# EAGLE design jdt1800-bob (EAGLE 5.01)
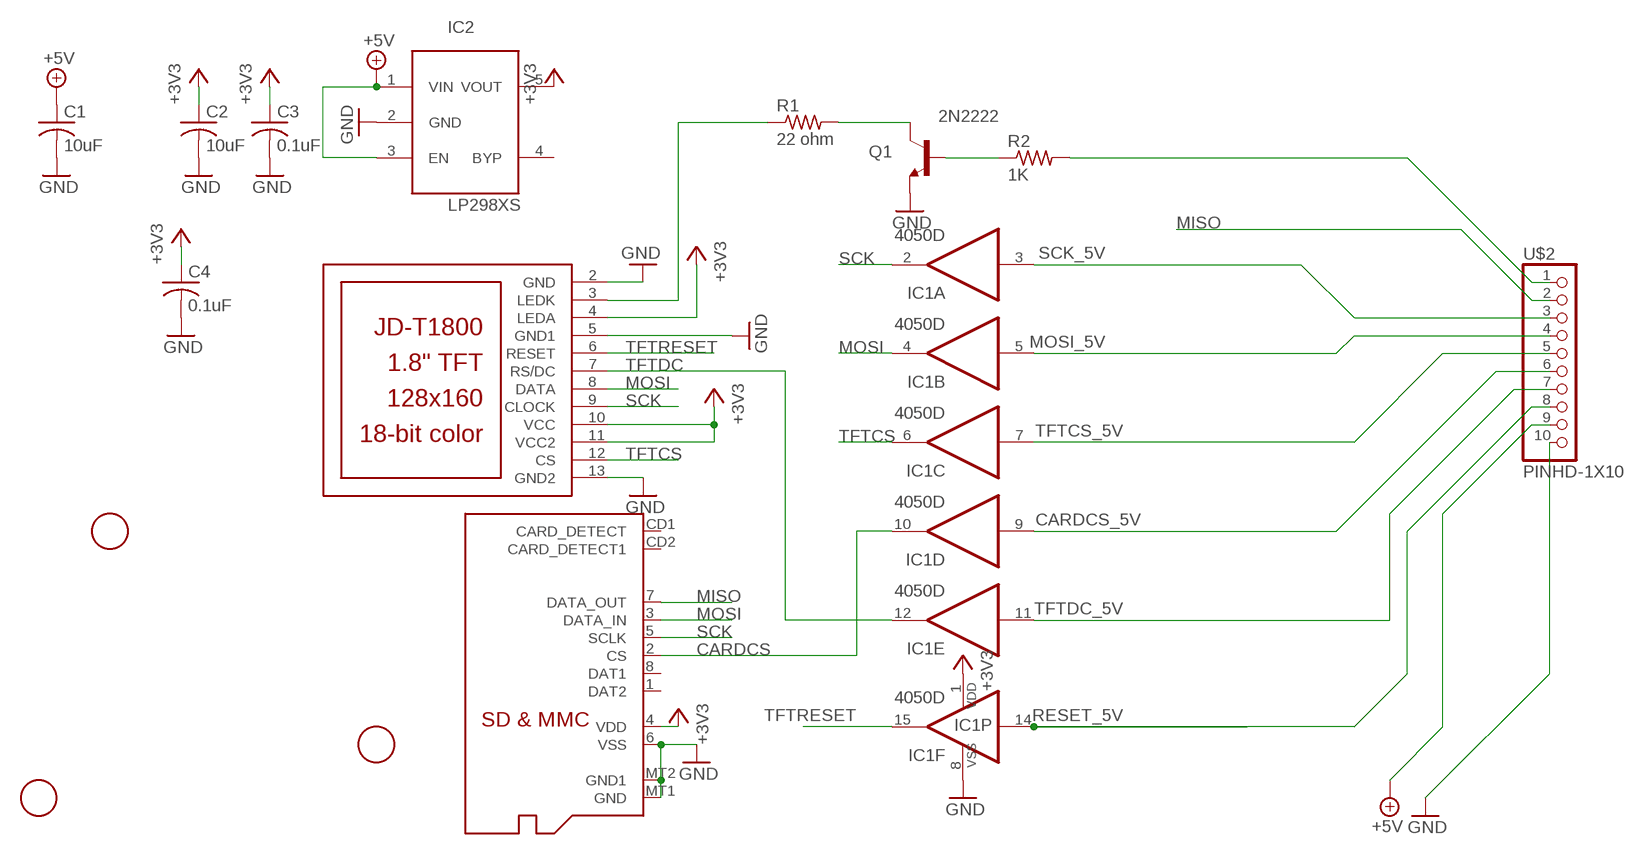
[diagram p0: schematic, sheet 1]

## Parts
C1  10uF  C-USC0805K  [C0805K]
C2  10uF  C-USC0805K  [C0805K]
C3  0.1uF  C-USC0805K  [C0805K]
C4  0.1uF  C-USC0805K  [C0805K]
IC1  4050D  [SO16]
IC2  LP298XS  [SOT23-5L]
Q1  2N2222  MMBT2222ALT1-NPN-SOT23-BEC  [SOT23-BEC]
Q2  MICROSD  [MICROSD]
R1  22 ohm  R-US_R0805  [R0805]
R2  1K  R-US_R0805  [R0805]
U$1  JD-T1800  [JD-T1800]
U$2  PINHD-1X10  [1X10-BIG]
U$3  FIDUCIAL  [FIDUCIAL_1MM]
U$4  FIDUCIAL  [FIDUCIAL_1MM]
U$5  FIDUCIAL  [FIDUCIAL_1MM]

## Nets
+3V3 [power]: C2.1 C3.1 C4.1 IC1.1(P:VDD) IC2.5(VOUT) Q2.4(VDD) U$1.4(LEDA) U$1.10(VCC) U$1.11(VCC2)
+5V [power]: C1.1 IC2.1(VIN) IC2.3(EN) U$2.9
CARDCS: IC1.10(D:O) Q2.2(CS)
CARDCS_5V: IC1.9(D:I) U$2.6
GND: C1.2 C2.2 C3.2 C4.2 IC1.8(P:VSS) IC2.2(GND) Q1.E Q2.6(VSS) Q2.MT1(GND) Q2.MT2(GND1) U$1.2(GND) U$1.5(GND1) U$1.13(GND2) U$2.10
MISO: Q2.7(DATA_OUT) U$2.2
MOSI: IC1.4(B:O) Q2.3(DATA_IN) U$1.8(DATA)
MOSI_5V: IC1.5(B:I) U$2.4
N$1: Q1.B R2.1
N$4: R1.1 U$1.3(LEDK)
N$5: Q1.C R1.2
N$6: R2.2 U$2.1
RESET_5V: IC1.14(F:I) U$2.8
SCK: IC1.2(A:O) Q2.5(SCLK) U$1.9(CLOCK)
SCK_5V: IC1.3(A:I) U$2.3
TFTCS: IC1.6(C:O) U$1.12(CS)
TFTCS_5V: IC1.7(C:I) U$2.5
TFTDC: IC1.12(E:O) U$1.7(RS/DC)
TFTDC_5V: IC1.11(E:I) U$2.7
TFTRESET: IC1.15(F:O) U$1.6(RESET)
Unconnected: IC2.4(BYP) Q2.1(DAT2) Q2.8(DAT1) Q2.CD1(CARD_DETECT) Q2.CD2(CARD_DETECT1)

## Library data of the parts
C1-C4 = rcl:C-US: CAPACITOR, American symbol
IC1 = 40xx:4050: Hex non-inverting BUFFER
IC2 = adafruit:LP298X
Q1 = transistor:*-NPN-: NPN Transistror BF959 corrected 2008.03.06
Q2 = adafruit:MICROSD: Micro-SD / Transflash card holder with SPI pinout For the 3M # 2908-05WB-MG and/or 4UCON #19656 push-push type
R1 R2 = adafruit:R-US_: RESISTOR, American symbol
U$1 = adafruit:JD-T1800
U$2 = adafruit:PINHD-1X10: Pin header 1x10 0.1" spacing With round pins
U$3-U$5 = adafruit:FIDUCIAL: For use by pick and place machines to calibrate the vision/machine, 1mm

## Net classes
1 power: width 0.406 mm

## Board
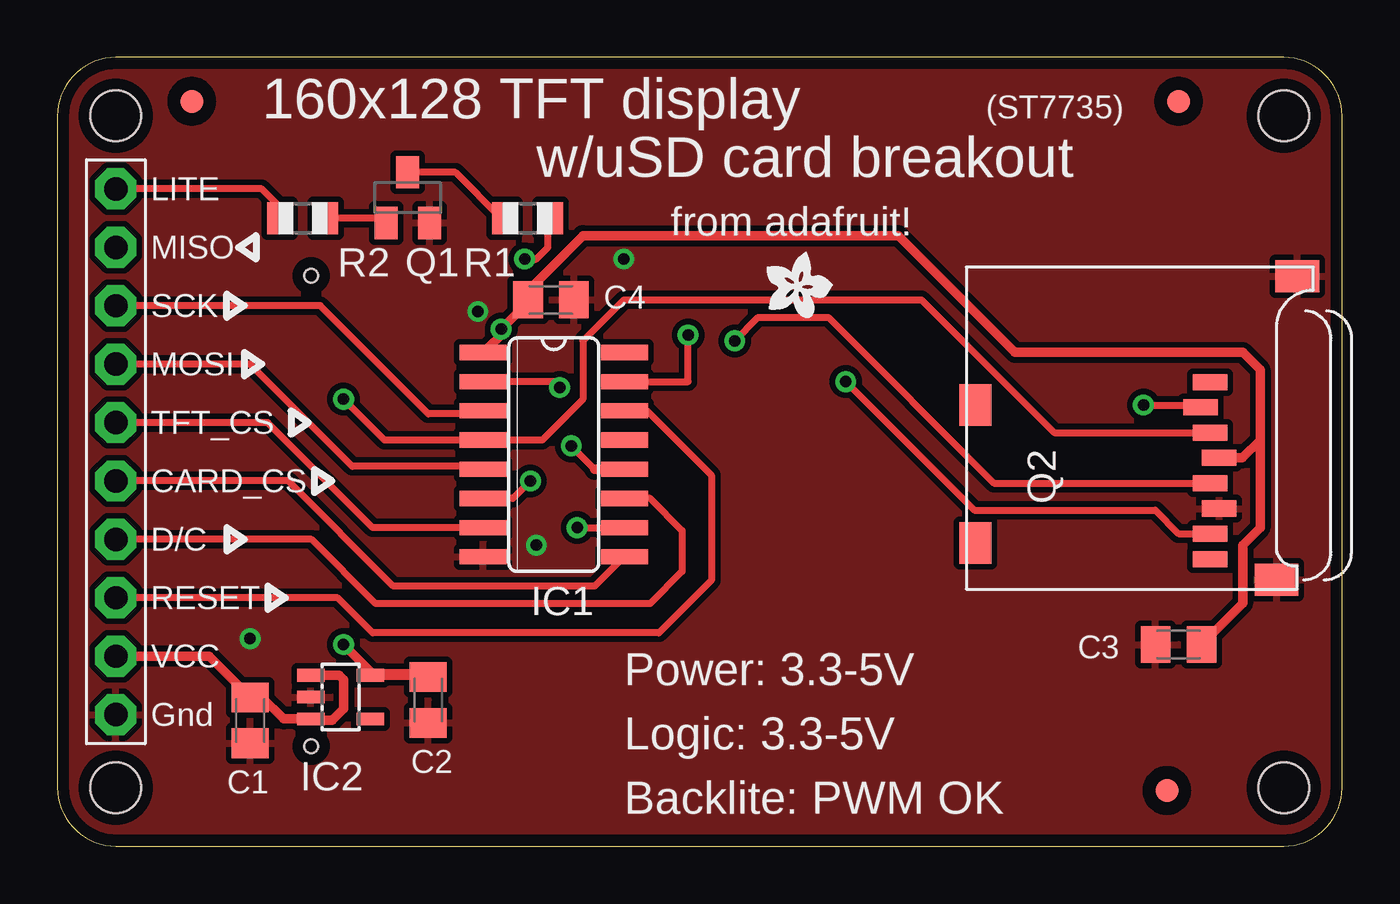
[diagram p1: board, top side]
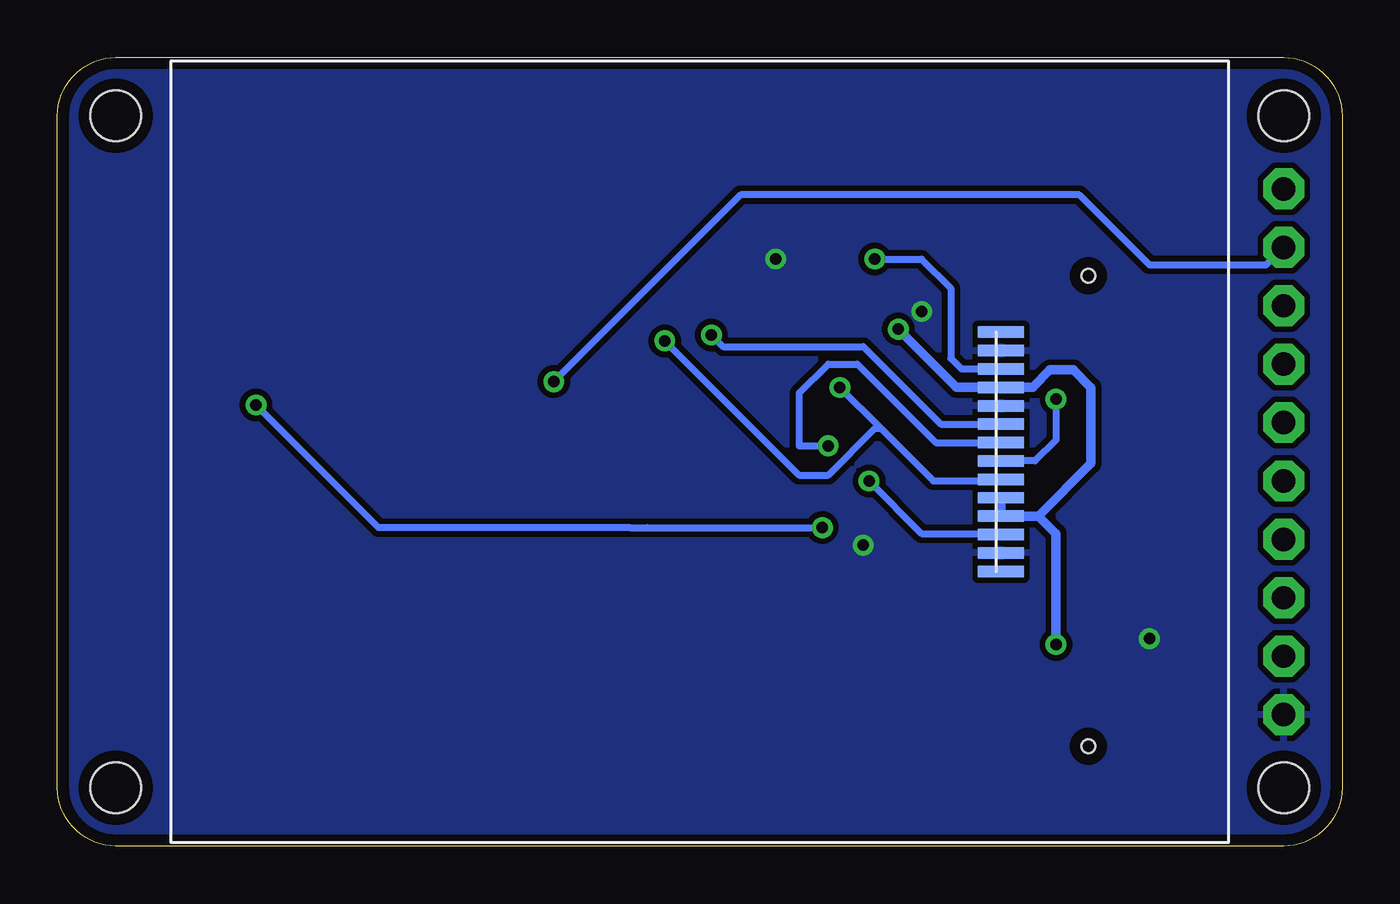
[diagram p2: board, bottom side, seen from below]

Size 55.88 x 34.29 mm. Coordinates in mm from the lower left corner, seen from the top.
Outline: 2.54,34.29 arc90 0,31.75 0,2.54 arc90 2.54,0 53.34,0 arc90 55.88,2.54 55.88,31.75 arc90 53.34,34.29 2.54,34.29
Copper layers (1*16): Top 0.035mm / dielectric 1.5mm / Bottom 0.035mm
Design rules "default *": minimum track width 10mil, minimum drill 14mil, track to track 10mil, track to pad 10mil, pad to pad 10mil, via to via 10mil, smd to smd 8mil, copper to edge 20mil, drill to drill 8mil, minimum pad ring 10mil, minimum via ring 8mil, stop-mask expansion 4mil, vias tented up to drill 20mil, thermal gap 10mil
Holes 2.2 mm at 2.54,31.75 2.54,2.54 53.34,2.54 53.34,31.75

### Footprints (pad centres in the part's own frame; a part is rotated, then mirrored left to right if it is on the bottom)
C0805K = smd 1.3 x 1.6: 1 -1,0; 2 1,0
SO16 = smd 0.66 x 2.032: 1 -4.445,-3.073; 2 -3.175,-3.073; 3 -1.905,-3.073; 4 -0.635,-3.073; 5 0.635,-3.073; 6 1.905,-3.073; 7 3.175,-3.073; 8 4.445,-3.073; 9 4.445,3.073; 10 3.175,3.073; 11 1.905,3.073; 12 0.635,3.073; 13 -0.635,3.073; 14 -1.905,3.073; 15 -3.175,3.073; 16 -4.445,3.073
SOT23-5L = smd 0.55 x 1.2: 1 -0.95,-1.3; 2 0,-1.3; 3 0.95,-1.3; 4 0.95,1.3; 5 -0.95,1.3
SOT23-BEC = smd 1 x 1.4: B -0.95,-1.1; C 0,1.1; E 0.95,-1.1
MICROSD = smd 0.7 x 1.5: 1 9,-10.64; 2 7.9,-10.24; 3 6.8,-10.64; 4 5.7,-11.04; 5 4.6,-10.64; 6 3.5,-11.04; 7 2.4,-10.64; 8 1.3,-10.64 | smd 1.8 x 1.4: CD1 2,-0.44; CD2 8,-0.44 | smd 1.4 x 1.9: MT1 0.4,-13.54; MT2 13.6,-14.44
R0805 = smd 1.1 x 1.4: 1 -1,0; 2 1,0
JD-T1800 = smd 0.5 x 2: 1 5.2,-13.1; 2 4.4,-13.1; 3 3.6,-13.1; 4 2.8,-13.1; 5 2,-13.1; 6 1.2,-13.1; 7 0.4,-13.1; 8 -0.4,-13.1; 9 -1.2,-13.1; 10 -2,-13.1; 11 -2.8,-13.1; 12 -3.6,-13.1; 13 -4.4,-13.1; 14 -5.2,-13.1 | hole 0.6: -12.8,-16.9; 7.65,-16.9
1X10-BIG = drill 1.016 pad 1.778 octagon: 1 -11.43,0; 2 -8.89,0; 3 -6.35,0; 4 -3.81,0; 5 -1.27,0; 6 1.27,0; 7 3.81,0; 8 6.35,0; 9 8.89,0; 10 11.43,0
FIDUCIAL_1MM = smd 1 x 1: 1 0,0

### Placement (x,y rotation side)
C1  8.38,5.46 270 top
C2  16.13,6.35 270 top
C3  48.77,8.76 180 top
C4  21.46,23.75 0 top
IC1  21.59,17.02 270 top
IC2  12.32,6.48 270 top
Q1  15.24,28.19 0 top
Q2  39.5,11.18 90 top
R1  20.45,27.3 180 top
R2  10.67,27.3 180 top
U$1  27.94,17.14 90 bottom
U$2  2.54,17.14 270 top
U$3  48.26,2.41 0 top
U$4  5.84,32.38 0 top
U$5  48.77,32.38 0 top
U$6  [ADAFRUIT200MIL]  32.26,24.51 270 top

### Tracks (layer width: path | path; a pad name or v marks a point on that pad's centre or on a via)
+3V3  (via drill 0.5)
  Top 0.406: 16.19,7.43 C2.1 | 16.19,7.43 IC2.5 | 16.19,7.43 16.26,7.49 13.72,7.49 v12.45,8.76 | IC1.1 18.54,21.46 19.56,22.48 v19.3,22.48 20.32,23.49 20.32,23.75 C4.1 20.57,23.75 20.57,24.26 22.86,26.54 36.58,26.54 41.66,21.46 51.56,21.46 52.32,20.7 52.32,17.65 | Q2.4 51.55,16.88 52.32,17.65 | C3.1 51.56,10.56 51.56,13.08 52.32,13.84 52.32,17.65
  Bottom 0.406: v12.45,8.76 12.45,13.59 13.21,14.35 | 13.21,14.35 14.73,14.35 | 14.73,14.35 14.74,14.34 U$1.11 | U$1.10 14.84,14.46 14.73,14.35 | 13.21,14.35 10.92,16.64 10.92,19.94 11.68,20.7 12.7,20.7 13.46,19.95 U$1.4 16.77,19.95 v19.3,22.48
+5V
  Top 0.406: U$2.9 6.6,8.25 8.38,6.48 C1.1 8.38,6.22 8.64,6.48 8.89,6.48 9.84,5.53 IC2.3 11.11,5.53 11.18,5.46 11.94,5.46 12.45,5.97 12.45,7.24 12.26,7.43 IC2.1
CARDCS  (via drill 0.5)
  Top 0.305: v22.61,13.84 IC1.10 | Q2.2 49.74,19.13 49.78,19.18 v47.24,19.18
  Bottom 0.305: v22.61,13.84 30.23,13.84 30.99,13.84 41.91,13.84 v47.24,19.18
CARDCS_5V
  Top 0.305: U$2.6 10.03,15.88 14.61,11.3 23.37,11.3 24.64,12.57 IC1.9
GND  (via drill 0.5)
  other vias: 18.29,23.24 24.64,25.53 8.38,9.02 20.83,13.08
  pour Top: 0,-0.64 0,34.92 55.88,34.92 55.88,-0.64
  pour Bottom: 0,-0.64 0,34.92 55.88,34.92 55.88,-0.64
MISO  (via drill 0.5)
  Top 0.305: Q2.7 50.28,13.58 50.29,13.59 48.77,13.59 47.75,14.61 39.88,14.61 v34.29,20.19
  Bottom 0.305: U$2.2 3.3,25.27 8.38,25.27 11.43,28.32 26.16,28.32 v34.29,20.19
MOSI  (via drill 0.5)
  Top 0.305: IC1.4 18.54,17.65 | v12.45,19.43 14.22,17.65 IC1.4 | IC1.4 21.08,17.65 22.86,19.43 22.86,21.97 24.64,23.75 37.59,23.75 43.37,17.98 Q2.3
  Bottom 0.305: U$1.8 13.35,16.75 12.45,17.65 v12.45,19.43
MOSI_5V
  Top 0.305: U$2.4 8.38,20.95 12.83,16.51 18.54,16.51 18.67,16.38 IC1.5
N$1
  Top 0.305: 14.44,27.09 14.48,27.05 | 14.44,27.09 Q1.B | R2.1 14.22,27.3 14.44,27.09
N$4  (via drill 0.5)
  Top 0.305: R1.1 21.34,27.3 21.34,26.04 20.83,25.53 v20.32,25.53
  Bottom 0.305: U$1.3 16.55,20.75 17.02,21.21 17.02,24.26 18.29,25.53 v20.32,25.53
N$5
  Top 0.305: R1.2 19.3,27.3 17.32,29.29 Q1.C
N$6
  Top 0.305: U$2.1 8.89,28.57 9.91,27.56 9.65,27.3 R2.2
RESET_5V
  Top 0.305: U$2.8 12.19,10.79 13.72,9.27 26.16,9.27 28.45,11.56 28.45,16.13 25.65,18.92 IC1.14 24.64,18.92
SCK  (via drill 0.5)
  Top 0.305: IC1.2 21.59,20.19 v21.84,19.94 | Q2.5 40.74,15.78 33.53,22.99 30.48,22.99 v29.46,21.97
  Bottom 0.305: U$1.9 14.91,15.88 17.78,15.88 20.07,18.16 | 20.07,18.16 v21.84,19.94 | 20.07,18.16 20.32,18.16 22.35,16.13 23.62,16.13 v29.46,21.97
SCK_5V
  Top 0.305: U$2.3 11.43,23.49 16.13,18.8 18.64,18.8 | 18.64,18.8 18.67,18.8 | IC1.3 18.64,18.8
TFTCS  (via drill 0.5)
  Top 0.305: IC1.6 19.81,15.11 v20.57,15.88
  Bottom 0.305: U$1.12 14.88,13.59 18.29,13.59 v20.57,15.88
TFTCS_5V
  Top 0.305: U$2.5 9.14,18.41 13.72,13.84 18.54,13.84 | IC1.7 18.54,13.84 | 18.54,13.84 18.67,13.72
TFTDC  (via drill 0.5)
  Top 0.305: v22.35,17.4 23.37,16.38
  Top 0.406: 23.37,16.38 IC1.12
  Bottom 0.305: v22.35,17.4 23.62,17.4 23.62,19.68 22.35,20.95 21.08,20.95 17.67,17.54 U$1.7
TFTDC_5V
  Top 0.305: U$2.7 11.05,13.33 13.84,10.54 25.78,10.54 27.18,11.94 27.18,13.72 25.78,15.11 IC1.11
TFTRESET  (via drill 0.5)
  Top 0.305: 24.89,20.19 IC1.15 27.43,20.19 v27.43,22.23
  Bottom 0.305: U$1.6 17.46,18.34 20.83,21.72 26.92,21.72 v27.43,22.23

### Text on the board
tPlace: 160x128 TFT display | (ST7735) | w/uSD card breakout | LITE | from adafruit! | MISO | SCK | MOSI | TFT_CS | CARD_CS | D/C | RESET | VCC | Power: 3.3-5V | Gnd | Logic: 3.3-5V | Backlite: PWM OK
